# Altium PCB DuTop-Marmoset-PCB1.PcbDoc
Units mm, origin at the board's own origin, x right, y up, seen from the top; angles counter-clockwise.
Board outline 16.1 x 27.6 mm, 4 copper layers (Top Signal, Layer 2 - VCC, Layer 3 - GND, Bottom Layer), stack 1.5 mm thick; 16 components, 12 nets, 55 pads, 23 vias.
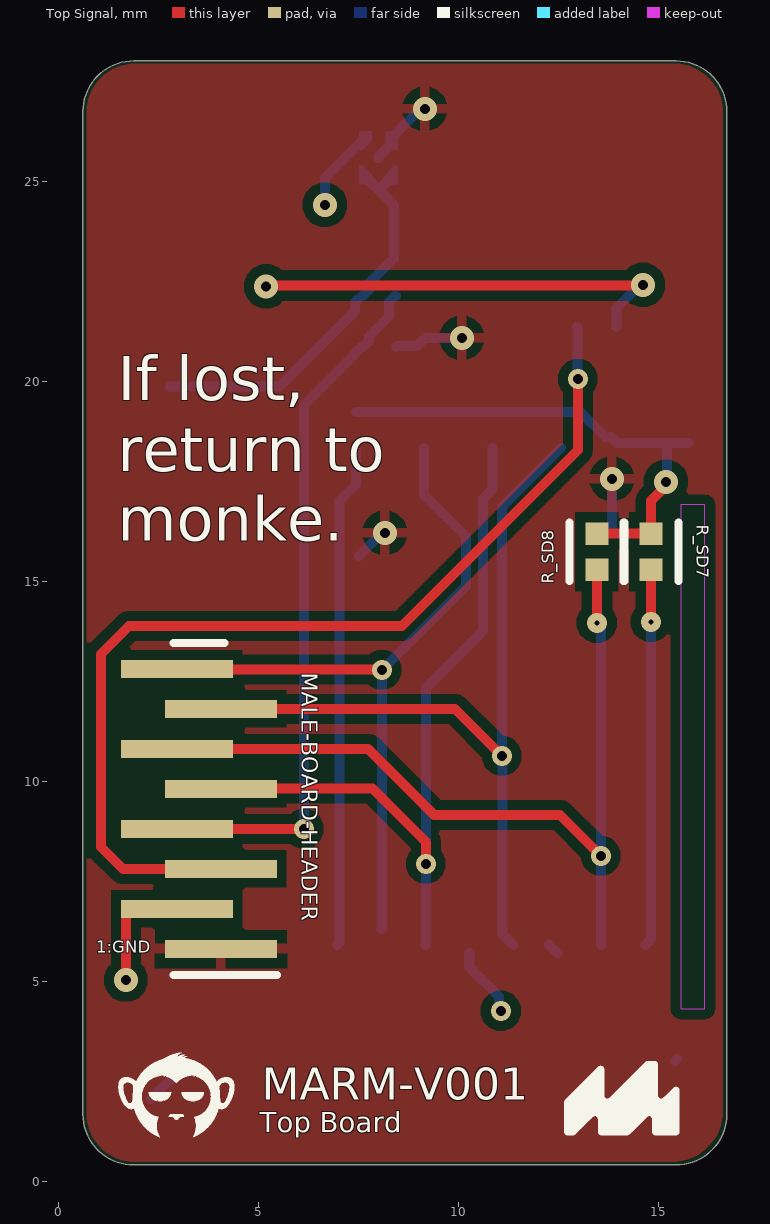
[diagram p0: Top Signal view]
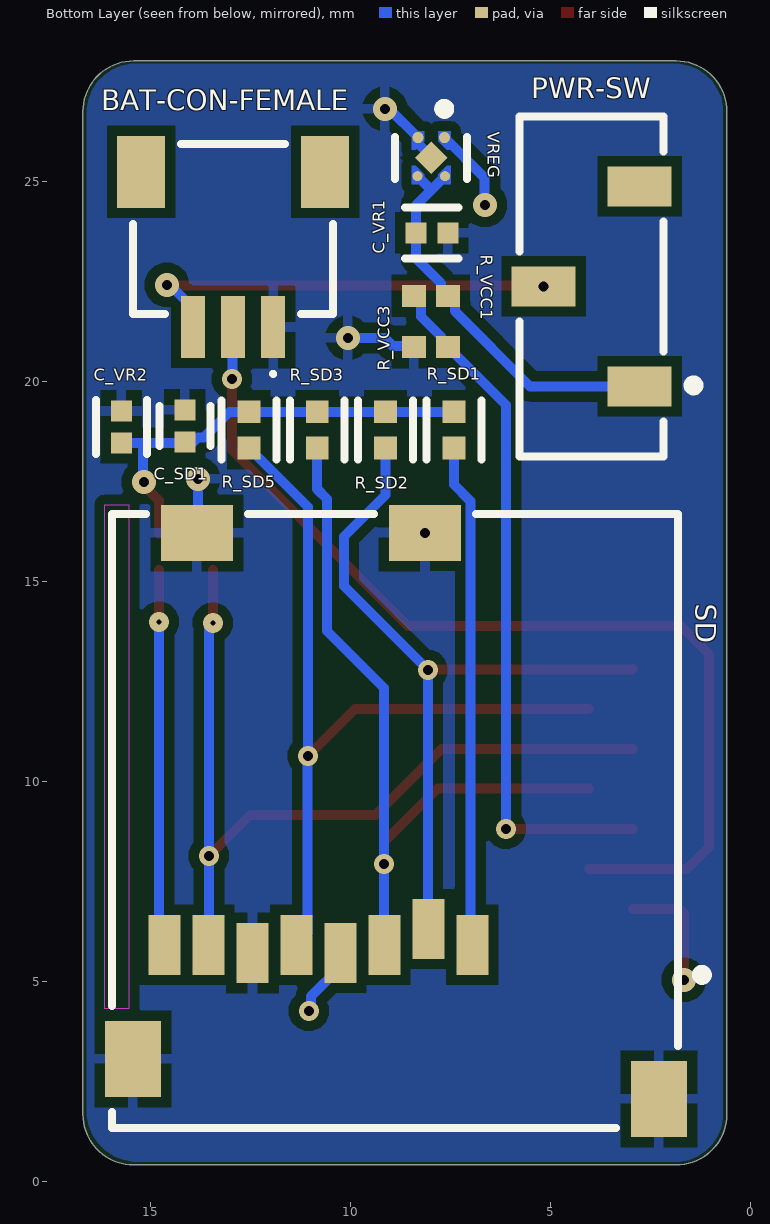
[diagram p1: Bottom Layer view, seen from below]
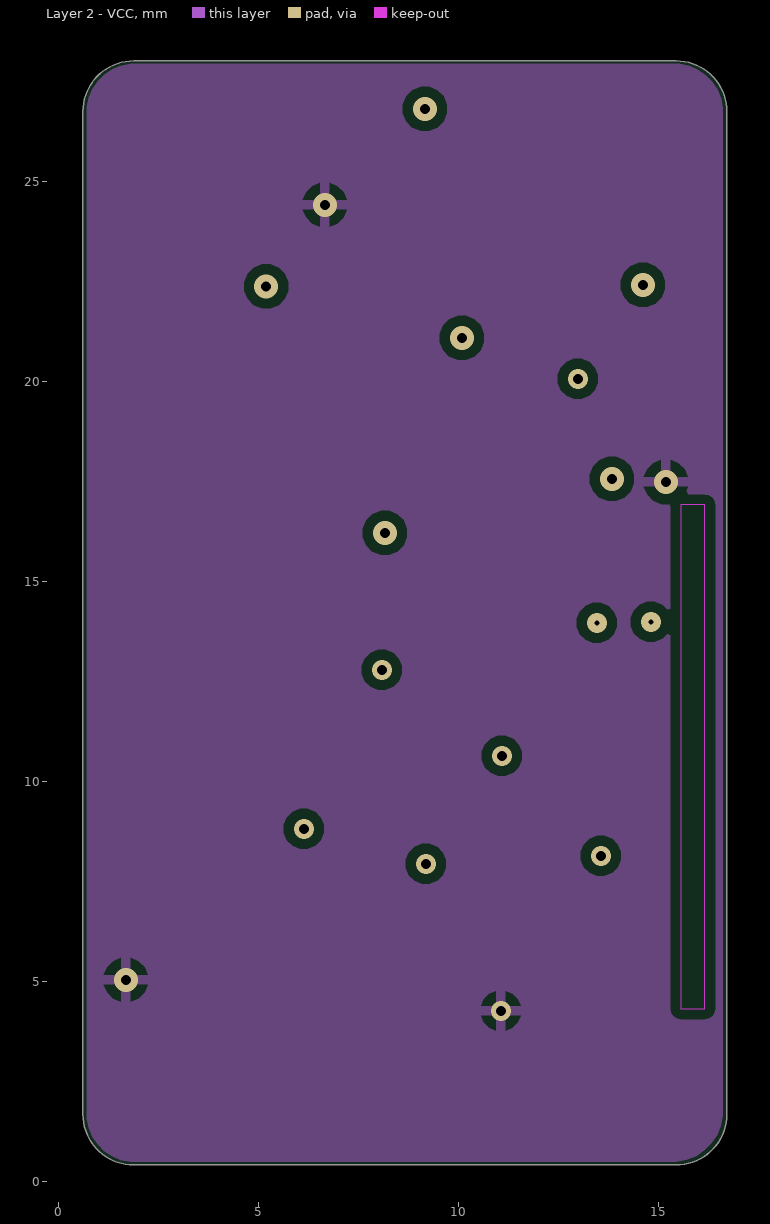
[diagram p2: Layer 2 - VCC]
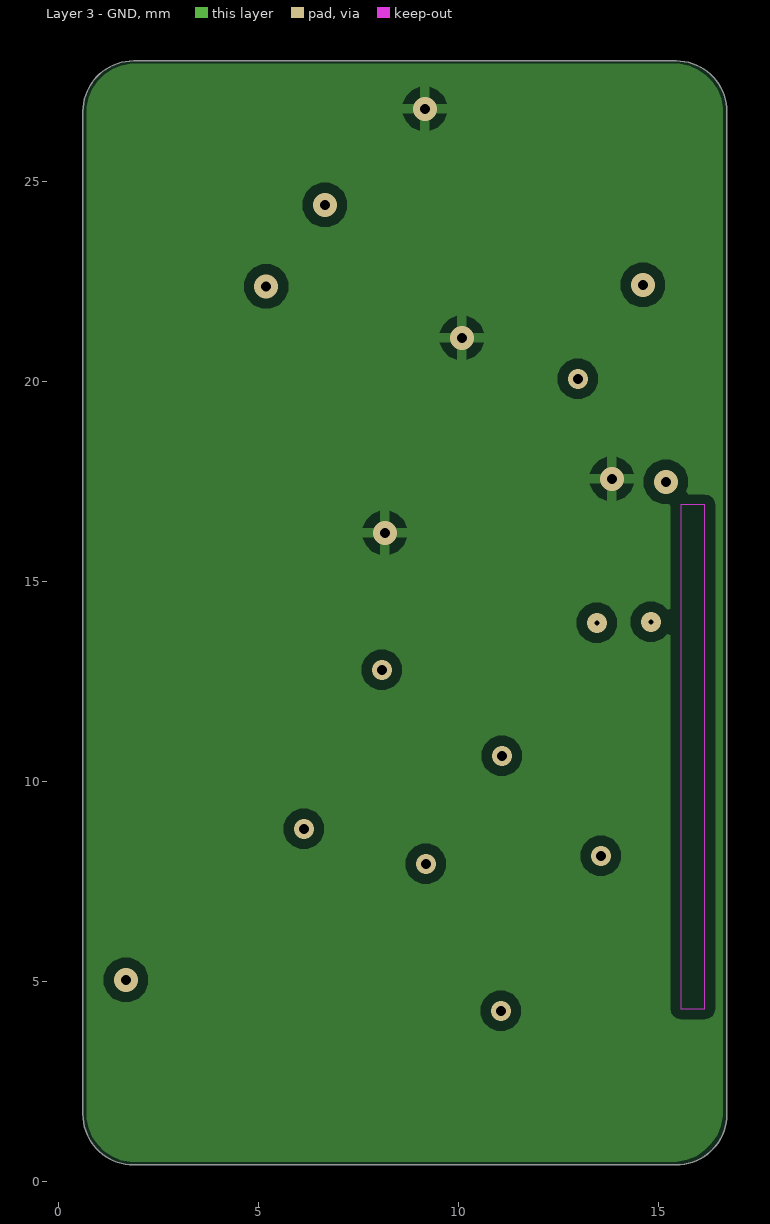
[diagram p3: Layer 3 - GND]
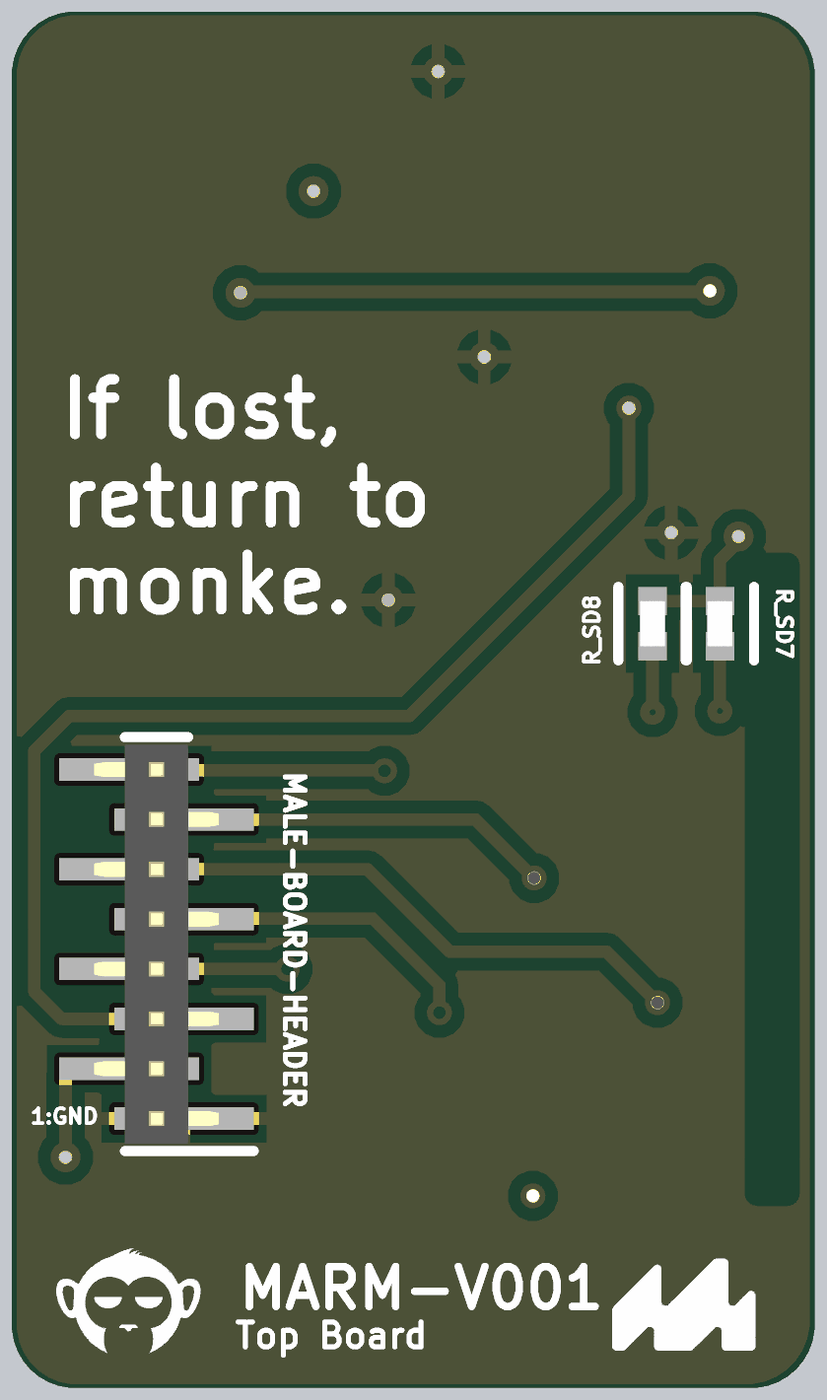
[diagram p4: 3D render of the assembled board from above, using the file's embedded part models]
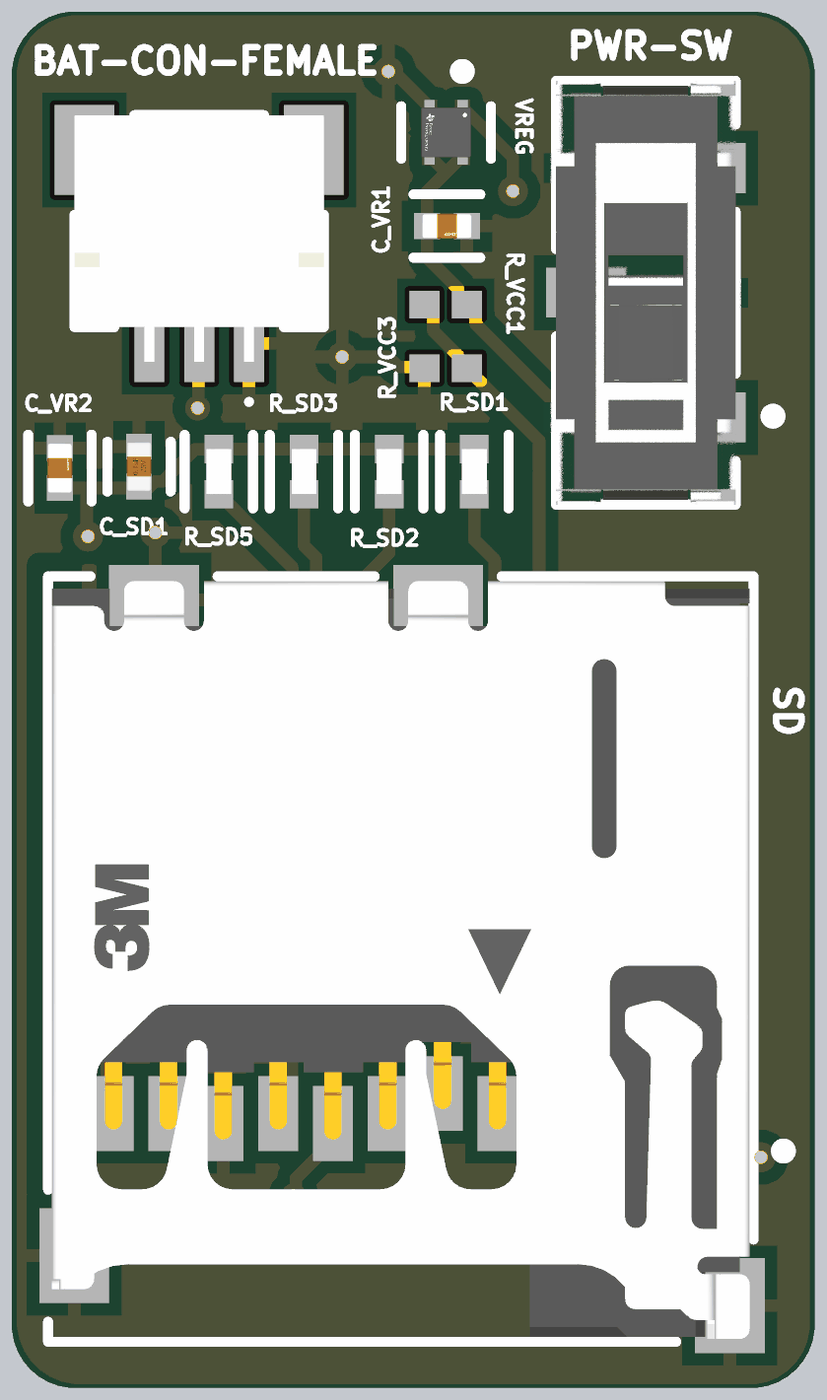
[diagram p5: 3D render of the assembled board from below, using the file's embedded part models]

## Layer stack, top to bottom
Top Solder: solder mask 0.012, FC-001, Dk 4
Top Solder: solder mask 0.0102, Solder Resist, Dk 3.5
Top Signal: signal copper 0.0175
Dielectric 2: prepreg 0.36, PP-006, Dk 4.1
Layer 2 - VCC: signal copper 0.0175
Dielectric 1: dielectric 0.71, FR-4, Dk 4.8
Layer 3 - GND: signal copper 0.0175
Dielectric 3: prepreg 0.36, PP-006, Dk 4.1
Bottom Layer: signal copper 0.0175
Flex Bottom Coverlay: solder mask 0.0102, Solder Resist, Dk 3.5
Flex Bottom Coverlay: solder mask 0.012, FC-001, Dk 4

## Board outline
0.6,1.695 0.6,26.755 cw(c1.87,26.755) 1.87,28.025 15.43,28.025 cw(c15.43,26.755) 16.7,26.755 16.7,1.695 cw(c15.43,1.695) 15.43,0.425 1.87,0.425 cw(c1.87,1.695)

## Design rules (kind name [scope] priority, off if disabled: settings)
Clearance Eurocircuits [All] p1: gap=0.25 ignorepadtopadclearanceinfootprint=TRUE except(0.11: Arc-Arc Arc-Track Arc-SMDPad Track-Track Track-SMDPad SMDPad-SMDPad SMDPad-Via; 0.125: THPad-Hole; 0.13: THPad-THPad Via-Via) // Marmoset Project
Clearance [All] p2: gap=0.254 ignorepadtopadclearanceinfootprint=FALSE
DiffPairsRouting [All] p1: maxlimit=0.254 minlimit=0.254 mostfreqgap=0.254 substack1={4CFAFDA6-F42D-4065-9748-95331561A070} toplayer_{4cfafda6-f42d-4065-9748-95331561a070}_minwidth=0.381 toplayer_{4cfafda6-f42d-4065-9748-95331561a070}_maxwidth=0.381 toplayer_{4cfafda6-f42d-4065-9748-95331561a070}_prefwidth=0.381 midlayer1_{4cfafda6-f42d-4065-9748-95331561a070}_minwidth=0.381 midlayer1_{4cfafda6-f42d-4065-9748-95331561a070}_maxwidth=0.381 midlayer1_{4cfafda6-f42d-4065-9748-95331561a070}_prefwidth=0.381 midlayer2_{4cfafda6-f42d-4065-9748-95331561a070}_minwidth=0.381 midlayer2_{4cfafda6-f42d-4065-9748-95331561a070}_maxwidth=0.381 midlayer2_{4cfafda6-f42d-4065-9748-95331561a070}_prefwidth=0.381 bottomlayer_{4cfafda6-f42d-4065-9748-95331561a070}_minwidth=0.381 bottomlayer_{4cfafda6-f42d-4065-9748-95331561a070}_maxwidth=0.381 bottomlayer_{4cfafda6-f42d-4065-9748-95331561a070}_prefwidth=0.381 toplayer_minwidth=0.381 toplayer_maxwidth=0.381 toplayer_prefwidth=0.381 midlayer1_minwidth=0.381 midlayer1_maxwidth=0.381 midlayer1_prefwidth=0.381 midlayer2_minwidth=0.381 midlayer2_maxwidth=0.381 midlayer2_prefwidth=0.381 bottomlayer_minwidth=0.381 bottomlayer_maxwidth=0.381 bottomlayer_prefwidth=0.381 maxuncoupledlength=12.7
PolygonConnect [All] p1: connectstyle=Relief reliefconductorwidth=0.254 reliefentries=4 polygonreliefangle="90 Angle" airgapwidth=0.254
RoutingVias [All] p1: holewidth=0.12 width=0.5 viastyle="Through Hole" minholewidth=0.1 minwidth=0.45 maxholewidth=0.15 maxwidth=0.6
SolderMaskExpansion [All] p1: expansion=0.102 istentingtop=FALSE
SupplyNets "Schematic Supply Nets_3" [InNet('GND')] p1: voltage=0.000
SupplyNets "Schematic Supply Nets_2" [InNet('VIN_SW')] p2: voltage=0.000
SupplyNets "Schematic Supply Nets_1" [InNet('VCC_3.3')] p3: voltage=0.000
Width Width_1 [All] p1: maxlimit=0.26 minlimit=0.09 preferedwidth=0.13 substack1={4CFAFDA6-F42D-4065-9748-95331561A070} toplayer_{4cfafda6-f42d-4065-9748-95331561a070}_minwidth=0.254 toplayer_{4cfafda6-f42d-4065-9748-95331561a070}_maxwidth=0.254 toplayer_{4cfafda6-f42d-4065-9748-95331561a070}_prefwidth=0.254 midlayer1_{4cfafda6-f42d-4065-9748-95331561a070}_minwidth=0.254 midlayer1_{4cfafda6-f42d-4065-9748-95331561a070}_maxwidth=0.254 midlayer1_{4cfafda6-f42d-4065-9748-95331561a070}_prefwidth=0.254 midlayer2_{4cfafda6-f42d-4065-9748-95331561a070}_minwidth=0.2 midlayer2_{4cfafda6-f42d-4065-9748-95331561a070}_maxwidth=0.254 midlayer2_{4cfafda6-f42d-4065-9748-95331561a070}_prefwidth=0.25 bottomlayer_{4cfafda6-f42d-4065-9748-95331561a070}_minwidth=0.2 bottomlayer_{4cfafda6-f42d-4065-9748-95331561a070}_maxwidth=0.3 bottomlayer_{4cfafda6-f42d-4065-9748-95331561a070}_prefwidth=0.25 minimp=50.000000 maximp=50.000000 favimp=50.000000
29 further rules are at their usual default settings.

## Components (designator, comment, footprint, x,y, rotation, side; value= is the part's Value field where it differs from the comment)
BAT-CON-FEMALE "SM03B-SRSS-TB(LF)(SN)" JST-SM03B-SRSS-TB_V 12.944,23.824 r0 bottom
C_SD1 "C0402C104J4RACTU" FP-C0402-BB-MFG 14.15,18.9 r90 bottom value="0.10 μF"
C_VR1 "C0402C105K8PACTU" FP-C0402C105K8PACTU-MFG 7.975,23.725 r180 bottom
C_VR2 "C0402C105K8PACTU" FP-C0402C105K8PACTU-MFG 15.738,18.871 r90 bottom
MALE-BOARD-HEADER "8POS 1.0MM PITCH PIN HEADER, TYP - BC032-08-A-2-0200-0200-L-B" MALE-BOARD-HEADER-8 3.5,9.325 r90 top
PWR-SW "JS102011JCQN" FP-JS102011JCQN-MFG 3.984,22.387 r90 bottom
R_SD1 "CRCW040220K0FKED" FP-CRCW0402-e3-IPC_B 7.425,18.8 r90 bottom
R_SD2 "CRCW040220K0FKED" FP-CRCW0402-e3-IPC_B 9.133,18.8 r90 bottom
R_SD3 "CRCW040220K0FKED" FP-CRCW0402-e3-IPC_B 10.842,18.8 r90 bottom
R_SD5 "CRCW040220K0FKED" FP-CRCW0402-e3-IPC_B 12.55,18.8 r90 bottom
R_SD7 "CRCW040220K0FKED" FP-CRCW0402-e3-IPC_B 13.45,15.752 r90 top
R_SD8 "CRCW040220K0FKED" FP-CRCW0402-e3-IPC_B 14.8,15.752 r90 top
R_VCC1 "RC0402JR-0720ML" RESC1005X40X25NL05T10 8,22.15 r180 bottom
R_VCC3 "RC0402JR-0720ML" RESC1005X40X25NL05T10 8,20.875 r180 bottom
SD "2908-05WB-MG" FP-2908-05WB-MG-MFG 8.9,9.025 r0 bottom
VREG "LP5907SNX-3.3/NOPB" FP-DQN0004A-MFG 7.991,25.602 r270 bottom

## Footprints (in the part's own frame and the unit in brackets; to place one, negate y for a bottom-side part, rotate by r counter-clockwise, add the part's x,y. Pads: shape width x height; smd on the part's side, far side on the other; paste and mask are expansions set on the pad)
FP-2908-05WB-MG-MFG [mm]
  rect 0.8x1.5 smd paste+0 mask+0: 1(-1.94,3.1) 2(-0.84,2.7) 3(0.26,3.1) 4(1.36,3.3) 5(2.46,3.1) 6(3.56,3.3) 7(4.66,3.1) 8(5.76,3.1)
  rect 1.4x1.9 smd paste+0 mask+0: 9(-6.6,6.95) 10(6.55,5.95)
  rect 1.8x1.4 smd paste+0 mask+0: 11(-0.75,-7.2) 12(4.95,-7.2)
  Keep-Out Layer region: 6.65,4.7 7.25,4.7 7.25,-7.9 6.65,-7.9
  silkscreen extent -7.8,-7.68 7.07,7.68, body extent -7,-7.58 7,7.62, height 2
FP-C0402-BB-MFG [mm]
  rect 0.52x0.52 smd paste+0 mask+0: 1(-0.4,0) 2(0.4,0)
  silkscreen extent -0.5,-0.64 0.5,0.64, body extent -0.5,-0.25 0.5,0.25, height 0.55
FP-C0402C105K8PACTU-MFG [mm]
  rect 0.52x0.52 smd paste+0 mask+0: 1(-0.4,0) 2(0.4,0)
  silkscreen extent -0.67,-0.64 0.67,0.64, body extent -0.5,-0.25 0.5,0.25, height 0.55
FP-CRCW0402-e3-IPC_B [mm]
  rect 0.568x0.572 smd paste+0 mask+0: 1(-0.452,0) 2(0.452,0)
  silkscreen extent -0.74,-0.69 0.74,0.69, body extent -0.5,-0.25 0.5,0.25, height 0.4
FP-DQN0004A-MFG [mm]
  round 0.279 smd paste-1000 mask-1000: 1(-0.505,0.33) 2(-0.505,-0.33)
  round 0.251 smd paste-1000 mask-1000: 3(0.459,-0.346) 4(0.459,0.346)
  rect 0.58x0.58 smd rot 135 paste-1000 mask-1000: 5(0,0)
  Top Signal region: -0.66,-0.485 -0.2,-0.485 -0.2,-0.385 -0.41,-0.175 -0.66,-0.175
  Top Signal region: 0.66,0.485 0.2,0.485 0.2,0.385 0.41,0.175 0.66,0.175
  Top Signal region: 0.66,-0.485 0.2,-0.485 0.2,-0.385 0.41,-0.175 0.66,-0.175
  Top Signal region: -0.66,0.485 -0.2,0.485 -0.2,0.385 -0.41,0.175 -0.66,0.175
  silkscreen extent -1.35,-0.9 0.53,0.9, body extent -0.5,-0.5 0.5,0.5, height 0.4
FP-JS102011JCQN-MFG [mm]
  rect 1x1.6 smd paste+0 mask+0: 1(-2.5,-1.2) 2(0,1.2) 3(2.5,-1.2)
  silkscreen extent -4.25,-2.67 4.25,1.8, body extent -4.25,-2.05 4.25,2.05, height 5.6
JST-SM03B-SRSS-TB_V [mm] "SMD, 3-Leads, Body 5x4.25mm, Pitch 1mm"
  rect 0.6x1.55 smd: 1(-1,2.45) 2(0,2.45) 3(1,2.45)
  rect 1.2x1.8 smd: MP1(-2.3,-1.425) MP2(2.3,-1.425)
  silkscreen extent -2.5,-2.12 2.5,3.67, body extent -2.5,-2.13 2.5,2.82, height 3.25
MALE-BOARD-HEADER-8 [mm]
  rect 0.45x2.8 smd: 1(-3.5,-0.55) 2(-2.5,0.55) 3(-1.5,-0.55) 4(-0.5,0.55) 5(0.5,-0.55) 6(1.5,0.55) 7(2.5,-0.55) 8(3.5,0.55)
  silkscreen extent -4.15,-1.95 4.15,0.64, body extent -4,-1.25 4,1.25, height 4
RESC1005X40X25NL05T10 [mm] "Chip Resistor, 2-Leads, Body 1.00x0.50mm, IPC Medium Density"
  rect 0.6x0.55 smd: 1(-0.425,0) 2(0.425,0)
  body extent -0.53,-0.27 0.53,0.28, height 0.4

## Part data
BAT-CON-FEMALE: library part CMP-2000-07077-1, "Male Header, Pitch 1 mm, 1 x 3 Position, Height 2.9 mm, -25 to 85 degC, RoHS, Tape and Reel", Manufacturer=JST, Package Description="Male Header, Pitch 1 mm, 1 x 3 Position, Height 2.9 mm", Package Reference=SM03B-SRSS-TB
C_SD1: library part CMP-1034-02068-3, "CAP CER 0.1UF 16V 5% X7R 0402", Capacitance="0.10 μF", Manufacturer=Kemet, Package=C0402-BB, Temperature="-55°C to +125°C", Temperature Characteristic=X7R, Temperature Coefficient=15%, Temperature Range High=+125°C, Temperature Range Low=-55°C, Tolerance=0.05, Voltage Rating="16 V"
C_VR1 C_VR2: library part CMP-2008-02081-2, "CAP CER 1UF 10V X5R 0402", Capacitance=1uF, Case Code (Imperial)=0402, Case Code (Metric)=1005, Dielectric=X5R, Dielectric Material=Ceramic, Max Operating Temperature=85°C, Min Operating Temperature=-55°C, Package Quantity=1, Tolerance=10%, Voltage=10V
MALE-BOARD-HEADER: library part MALE-BOARD-HEADER-8P, Supplier Part Number 1=2073-BC032-08-A-2-0200-0200-L-BCT-ND
PWR-SW: library part CMP-10038-000010-1, "SWITCH SLIDE SPDT 300MA 6V", Current Rating=300mA, Max Operating Temperature=85°C, Min Operating Temperature=-40°C, Voltage Rating (DC)=6V
R_SD1 R_SD2 R_SD3 R_SD5 R_SD7 R_SD8: library part CMP-2002-08356-2, "RES Thick Film, 20kΩ, 1%, 0.063W, 100ppm/°C, 0402", Case Code (Imperial)=0402, Case Code (Metric)=1005, Max Operating Temperature=155°C, Max Power Dissipation=63mW, Min Operating Temperature=-55°C, Package Quantity=10, Resistance=20kR, Temperature Coefficient=100ppm/°C, Tolerance=1%, Voltage Rating=50V
R_VCC1 R_VCC3: library part CMP-2002-06961-1, Manufacturer=Yageo
SD: library part CMP-2000-05030-2, "CONN MICRO SD CARD PUSH-PUSH R/A", Current Rating=500mA, Flammability Rating="UL94 V-0", Max Operating Temperature=85°C, Min Operating Temperature=-25°C, Package Quantity=3000
VREG: library part CMP-04917-000059-2, "None", Dropout Voltage=250mV, Max Input Voltage=5.5V, Max Operating Temperature=125°C, Max Output Current=250mA, Min Input Voltage=2.2V, Min Operating Temperature=-40°C, Nominal Output Voltage=3.3V, Output Voltage Accuracy=2%, Power Supply Rejection Ratio (PSRR)=82dB, Quiescent Current=250uA

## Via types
v1: diameter 0.6, hole 0.25, Top Signal to Bottom Layer, 9 vias
v2: diameter 0.5, hole 0.25, Top Signal to Bottom Layer, 4 vias
v3: diameter 0.5, hole 0.25, Top Signal to Layer 3 - GND, 3 vias
v4: diameter 0.5, hole 0.25, Layer 3 - GND to Bottom Layer, 3 vias
v5: diameter 0.5, hole 0.12, Layer 3 - GND to Bottom Layer, 2 vias
v6: diameter 0.5, hole 0.12, Top Signal to Layer 3 - GND, 2 vias

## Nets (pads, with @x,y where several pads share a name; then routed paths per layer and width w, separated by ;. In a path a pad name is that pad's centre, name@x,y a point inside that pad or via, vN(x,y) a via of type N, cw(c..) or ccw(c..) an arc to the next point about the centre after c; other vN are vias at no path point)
BAT_TEMP: BAT-CON-FEMALE.2 MALE-BOARD-HEADER.3 | length 25.2
  Top Signal w0.25: MALE-BOARD-HEADER.3 1.6,7.825 1.05,8.375 1.05,13.2 1.75,13.9 8.575,13.9 12.975,18.3 v2(12.975,20.075)
  Bottom Layer w0.25: BAT-CON-FEMALE.2 12.96,21.358 12.96,20.09 v2(12.975,20.075)
GND: BAT-CON-FEMALE.1 C_SD1.2 C_VR1.2 C_VR2.2 MALE-BOARD-HEADER.1 R_VCC3.1 SD.6 SD.9 SD.10 SD.11 SD.12 VREG.2 VREG.5 | length 6.7
  Bottom Layer w0.25: SD.9 SD.9@2.875,2.65 ; SD.11@7.5,15.65 8.075,16.225 v1(8.15,16.225) ; VREG.5 7.991,25.627 8.271,25.907 ; VREG.2 9.039,26.825 v1(9.15,26.825) ; R_VCC3.1 8.45,20.9 8.954,20.9 9.153,21.1 v1(10.075,21.1) ; SD.6@12.25,5.935 SD.6 ; v1(13.825,17.575) 13.825,16.25 SD.12 ; SD.10@15.4,3.025 SD.10
NetBAT-CON-FEMALE_3: BAT-CON-FEMALE.3 PWR-SW.2 | length 10.8
  Top Signal w0.25: v1(5.184,22.387) 5.203,22.406 14.581,22.406 v1(14.6,22.425)
  Bottom Layer w0.25: BAT-CON-FEMALE.3 13.944,21.849 14.52,22.425 v1(14.6,22.425)
NetR_SD1_1: R_SD1.1 SD.1 | length 12.6
  Bottom Layer w0.25: SD.1 7.015,5.98 7.015,17.022 7.425,17.432 R_SD1.1
NetR_SD8_1: R_SD8.1 SD.8 | length 9.4
  Top Signal w0.25: v6(14.8,14) 14.8,14.025 R_SD8.1
  Bottom Layer w0.25: SD.8 14.8,6.065 v6(14.8,14)
  other v5: 14.8,14
SDHC_CS: MALE-BOARD-HEADER.8 R_SD2.1 SD.2 | length 18.5
  Top Signal w0.25: MALE-BOARD-HEADER.8 2.963,12.812 8.062,12.812 v4(8.075,12.8)
  Bottom Layer w0.25: SD.2 8.075,6.34 v4(8.075,12.8) 10.175,14.9 10.175,16.132 9.133,17.174 R_SD2.1
  other v3: 8.075,12.8
SDHC_MISO: MALE-BOARD-HEADER.6 R_SD7.1 SD.7 | length 21.1
  Top Signal w0.25: MALE-BOARD-HEADER.6 7.734,10.825 9.384,9.175 12.525,9.175 v2(13.55,8.15) ; v6(13.45,13.975) 13.45,14 R_SD7.1
  Bottom Layer w0.25: v6(13.45,13.975) 13.45,13.907 13.55,13.807 13.55,5.935 SD.7
  other v5: 13.45,13.975
SDHC_MOSI: MALE-BOARD-HEADER.5 R_SD3.1 SD.3 | length 19.4
  Top Signal w0.25: MALE-BOARD-HEADER.5 4.063,9.837 7.838,9.837 9.175,8.5 v4(9.175,7.95)
  Bottom Layer w0.25: SD.3 9.175,5.94 v4(9.175,7.95) 9.175,12.35 10.6,13.775 10.6,17.075 10.842,17.317 R_SD3.1
  other v3: 9.175,7.95
SDHC_SCLK: MALE-BOARD-HEADER.7 R_SD5.1 SD.5 | length 20.7
  Top Signal w0.25: MALE-BOARD-HEADER.7 9.9,11.825 v2(11.075,10.65)
  Bottom Layer w0.25: SD.5 11.085,6.2 11.085,10.64 v2(11.075,10.65) 11.075,16.873 R_SD5.1
VBAT_HALF: MALE-BOARD-HEADER.4 R_VCC1.1 R_VCC3.2 | length 17.5
  Top Signal w0.25: MALE-BOARD-HEADER.4 v3(6.125,8.825)
  Bottom Layer w0.25: v3(6.125,8.825) 6.125,19.425 7.4,20.7 7.4,20.725 7.55,20.875 7.6,20.875 7.75,21.025 7.75,21.132 8.25,21.632 8.25,22 8.4,22.15 R_VCC1.1
  other v4: 6.125,8.825
VCC_3.3: C_SD1.1 C_VR2.1 MALE-BOARD-HEADER.2 R_SD1.2 R_SD2.2 R_SD3.2 R_SD5.2 R_SD7.2 R_SD8.2 SD.4 VREG.1 | length 19.3
  Top Signal w0.25: v1(1.675,5.05) 1.675,6.725 1.775,6.825 MALE-BOARD-HEADER.2 ; R_SD7.2 R_SD8.2 14.8,17.03 15.175,17.405 v1(15.175,17.5)
  Bottom Layer w0.25: v1(6.65,24.425) 6.654,24.429 6.654,25.1 VREG.1 ; R_SD1.2 R_SD2.2 R_SD3.2 R_SD5.2 ; SD.4 10.26,5.375 11.002,4.633 11.002,4.323 v2(11.05,4.275) ; R_SD5.2@12.55,19.246 13.036,19.246 13.676,18.606 13.825,18.606 13.96,18.471 15.2,18.471 ; v1(15.175,17.5) 15.2,17.525 15.2,18.471 ; C_VR2.1 15.2,18.471
VIN_SW: C_VR1.1 PWR-SW.1 R_VCC1.2 VREG.3 VREG.4 | length 9.8
  Bottom Layer w0.25: PWR-SW.1 5.519,19.887 7.4,21.768 7.4,22 R_VCC1.2@7.459,22.059 ; R_VCC1.2 7.6,22.15 7.75,22.3 7.75,22.465 8.375,23.09 8.375,24.413 VREG.4 ; 8.01,24.816 VREG.3
pads on no net: BAT-CON-FEMALE.MP1 BAT-CON-FEMALE.MP2 PWR-SW.3

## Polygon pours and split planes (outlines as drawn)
GND on Bottom Layer "GND_L04_P005" (solid, remove dead copper, pour order 5): 15.325,0.5 1.9,0.5 cw(c1.9,1.7) 0.7,1.7 0.7,26.75 cw(c1.9,26.75) 1.9,27.95 8.55,27.95 15.4,27.95 cw(c15.388,26.738) 16.6,26.725 16.6,1.775 cw(c15.325,1.775)
VCC_3.3 on Layer 2 - VCC "VCC_3.3_L02_P006" (solid, remove dead copper, pour order 6): 15.325,0.5 1.9,0.5 cw(c1.9,1.7) 0.7,1.7 0.7,26.75 cw(c1.9,26.75) 1.9,27.95 8.55,27.95 15.4,27.95 cw(c15.388,26.738) 16.6,26.725 16.6,1.775 cw(c15.325,1.775)
GND on Layer 3 - GND "GND_L03_P007" (solid, remove dead copper, pour order 7): 15.325,0.5 1.9,0.5 cw(c1.9,1.7) 0.7,1.7 0.7,26.75 cw(c1.9,26.75) 1.9,27.95 8.55,27.95 15.4,27.95 cw(c15.388,26.738) 16.6,26.725 16.6,1.775 cw(c15.325,1.775)
GND on Top Signal "GND_L01_P004" (solid, remove dead copper, pour order 4): 15.325,0.5 1.9,0.5 cw(c1.9,1.7) 0.7,1.7 0.7,26.75 cw(c1.9,26.75) 1.9,27.95 8.55,27.95 15.4,27.95 cw(c15.388,26.738) 16.6,26.725 16.6,1.775 cw(c15.325,1.775)

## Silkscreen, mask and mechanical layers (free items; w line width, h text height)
Flex Top Overlay:
  drawing of 5 lines, arcs and shapes, not listed
  text "If lost," at 1.472,19.542 h1.1
  text "return to" at 1.472,17.767 h1.1
  text "monke." at 1.472,16.025 h1.1
  text "1:GND" at 0.93,5.73 h0.3
  text "MARM-V001" at 5.075,2.05 h0.8
  text "Top Board" at 5.025,1.242 h0.5
Mechanical 1:
  lines w0.15: 0.6,1.695 ccw(c1.87,1.695) 1.87,0.425 15.43,0.425 ccw(c15.43,1.695) 16.7,1.695 16.7,26.755 ccw(c15.43,26.755) 15.43,28.025 1.87,28.025 ccw(c1.87,26.755) 0.6,26.755 0.6,12.895 0.6,10.05 0.6,1.695 ; 2.25,5.325 2.25,13.325 4.75,13.325 4.75,5.325 2.25,5.325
